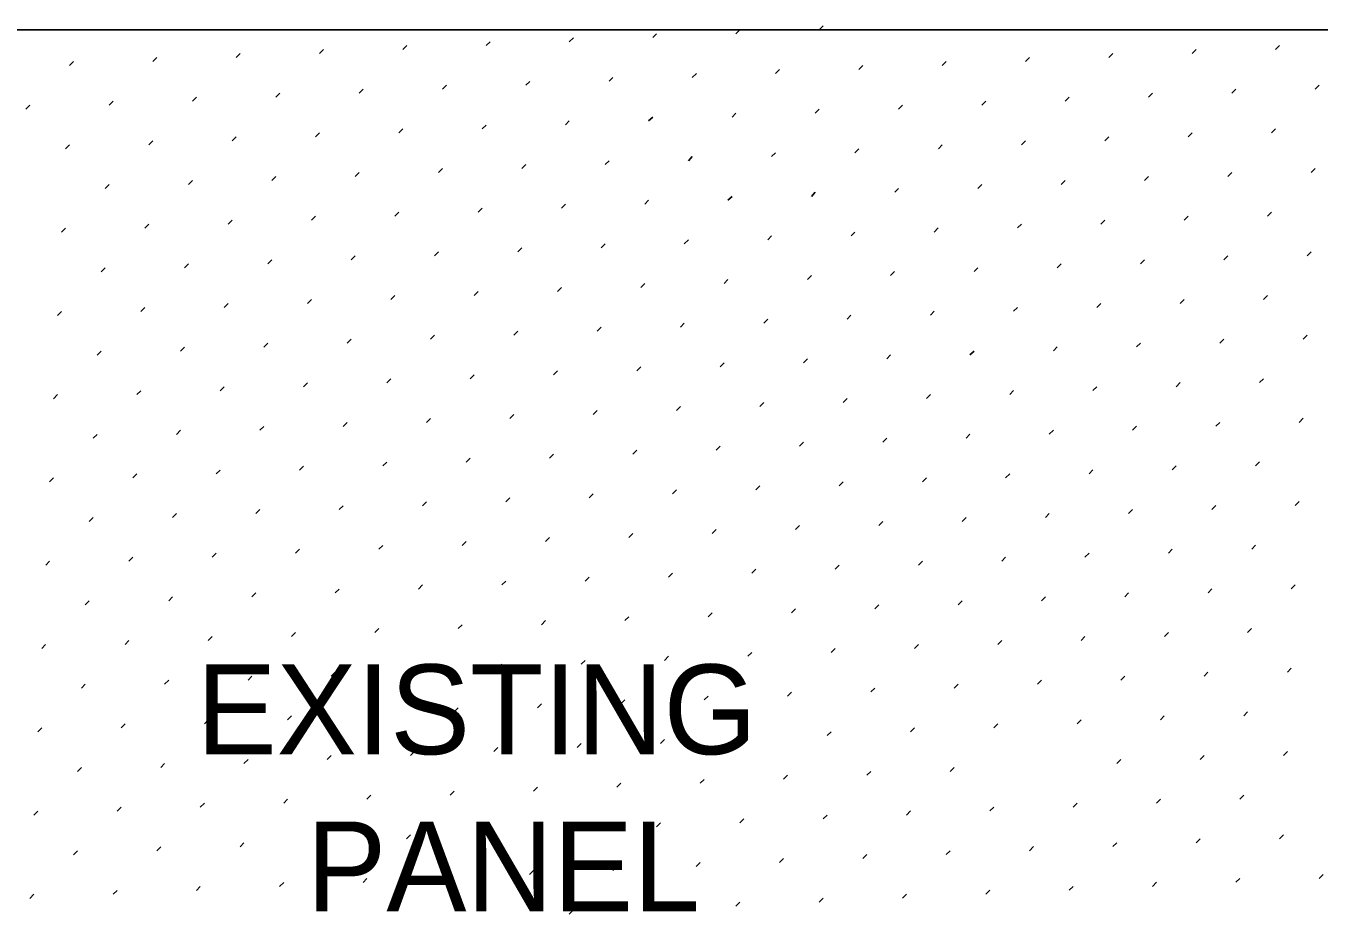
# Model space of a CAD drawing. Extents: x 49991.4 to 50021, y 49987.6 to 50011.4.
# Drawn here: x 50012.199 to 50013.352, y 49997.002 to 49997.794 of the extents above; entities that cross this region are included whole.
import ezdxf

# ---------------------------------------------------------------- set-up
doc = ezdxf.new("R2010")
doc.units = 0
for name, color, linetype in [('Level 1', 7, 'Continuous'), ('Level 10', 7, 'Continuous'), ('Level 2', 7, 'Continuous')]:
    doc.layers.add(name, color=color, linetype=linetype)

msp = doc.modelspace()

# ---------------------------------------------------------------- linework, layer by layer
at = {"layer": 'Level 1'}
msp.add_line((50011.6848, 49997.7903), (50015.1301, 49997.7903), dxfattribs=at)
at = {"layer": 'Level 10'}
for p, q in [((50012.9063, 49997.7902), (50012.9098, 49997.7938)), ((50012.6093, 49997.7761), (50012.6128, 49997.7796)), ((50012.6835, 49997.7796), (50012.6871, 49997.7831)), ((50012.7578, 49997.7832), (50012.7613, 49997.7867)), ((50012.832, 49997.7867), (50012.8356, 49997.7902)), ((50012.3865, 49997.7654), (50012.39, 49997.769)), ((50012.4608, 49997.769), (50012.4643, 49997.7725)), ((50012.535, 49997.7725), (50012.5386, 49997.7761)), ((50013.1644, 49997.7655), (50013.1679, 49997.769)), ((50013.2387, 49997.7691), (50013.2422, 49997.7726)), ((50013.3129, 49997.7726), (50013.3164, 49997.7761)), ((50012.238, 49997.7584), (50012.2415, 49997.7619)), ((50012.3123, 49997.7619), (50012.3158, 49997.7654)), ((50012.9416, 49997.7549), (50012.9452, 49997.7584)), ((50013.0159, 49997.7584), (50013.0194, 49997.762)), ((50013.0901, 49997.762), (50013.0937, 49997.7655)), ((50012.7189, 49997.7443), (50012.7224, 49997.7478)), ((50012.7931, 49997.7478), (50012.7967, 49997.7513)), ((50012.8674, 49997.7513), (50012.8709, 49997.7549)), ((50012.4219, 49997.7301), (50012.4254, 49997.7336)), ((50012.4961, 49997.7336), (50012.4997, 49997.7372)), ((50012.5704, 49997.7372), (50012.5739, 49997.7407)), ((50012.6446, 49997.7407), (50012.6482, 49997.7442)), ((50013.1998, 49997.7302), (50013.2033, 49997.7337)), ((50013.274, 49997.7337), (50013.2775, 49997.7372)), ((50013.3483, 49997.7372), (50013.3518, 49997.7408)), ((50012.1991, 49997.7195), (50012.2026, 49997.723)), ((50012.2734, 49997.723), (50012.2769, 49997.7265)), ((50012.3476, 49997.7265), (50012.3512, 49997.7301)), ((50012.977, 49997.7195), (50012.9805, 49997.7231)), ((50013.0512, 49997.7231), (50013.0548, 49997.7266)), ((50013.1255, 49997.7266), (50013.129, 49997.7301)), ((50012.7542, 49997.7089), (50012.7578, 49997.7124)), ((50012.8285, 49997.7124), (50012.832, 49997.716)), ((50012.9027, 49997.716), (50012.9063, 49997.7195)), ((50012.5315, 49997.6983), (50012.535, 49997.7018)), ((50012.6057, 49997.7018), (50012.6093, 49997.7053)), ((50012.68, 49997.7054), (50012.6835, 49997.7089)), ((50013.3094, 49997.6983), (50013.3129, 49997.7019)), ((50012.2345, 49997.6841), (50012.238, 49997.6876)), ((50012.3087, 49997.6876), (50012.3123, 49997.6912)), ((50012.383, 49997.6912), (50012.3865, 49997.6947)), ((50012.4572, 49997.6947), (50012.4608, 49997.6983)), ((50013.0124, 49997.6842), (50013.0159, 49997.6877)), ((50013.0866, 49997.6877), (50013.0901, 49997.6912)), ((50013.1609, 49997.6913), (50013.1644, 49997.6948)), ((50013.2351, 49997.6948), (50013.2386, 49997.6983)), ((50012.7896, 49997.6735), (50012.7931, 49997.6771)), ((50012.8638, 49997.6771), (50012.8674, 49997.6806)), ((50012.9381, 49997.6806), (50012.9416, 49997.6842)), ((50012.5668, 49997.6629), (50012.5704, 49997.6664)), ((50012.6411, 49997.6665), (50012.6446, 49997.67)), ((50012.7153, 49997.67), (50012.7189, 49997.6735)), ((50013.3447, 49997.663), (50013.3483, 49997.6665)), ((50012.3441, 49997.6523), (50012.3476, 49997.6558)), ((50012.4183, 49997.6558), (50012.4219, 49997.6594)), ((50012.4926, 49997.6594), (50012.4961, 49997.6629)), ((50013.122, 49997.6524), (50013.1255, 49997.6559)), ((50013.1962, 49997.6559), (50013.1997, 49997.6594)), ((50013.2705, 49997.6594), (50013.274, 49997.663)), ((50012.2698, 49997.6487), (50012.2734, 49997.6523)), ((50012.8249, 49997.6382), (50012.8285, 49997.6417)), ((50012.8992, 49997.6417), (50012.9027, 49997.6453)), ((50012.9735, 49997.6453), (50012.977, 49997.6488)), ((50013.0477, 49997.6488), (50013.0512, 49997.6523)), ((50012.6022, 49997.6276), (50012.6057, 49997.6311)), ((50012.6764, 49997.6311), (50012.68, 49997.6346)), ((50012.7507, 49997.6346), (50012.7542, 49997.6382)), ((50012.3794, 49997.6169), (50012.383, 49997.6205)), ((50012.4537, 49997.6205), (50012.4572, 49997.624)), ((50012.5279, 49997.624), (50012.5315, 49997.6276)), ((50013.1573, 49997.617), (50013.1609, 49997.6205)), ((50013.2316, 49997.6205), (50013.2351, 49997.6241)), ((50013.3058, 49997.6241), (50013.3094, 49997.6276)), ((50012.2309, 49997.6098), (50012.2345, 49997.6134)), ((50012.3052, 49997.6134), (50012.3087, 49997.6169)), ((50012.9346, 49997.6064), (50012.9381, 49997.6099)), ((50013.0088, 49997.6099), (50013.0123, 49997.6135)), ((50013.0831, 49997.6135), (50013.0866, 49997.617)), ((50012.6375, 49997.5922), (50012.6411, 49997.5957)), ((50012.7118, 49997.5957), (50012.7153, 49997.5993)), ((50012.786, 49997.5993), (50012.7896, 49997.6028)), ((50012.8603, 49997.6028), (50012.8638, 49997.6064)), ((50012.4148, 49997.5816), (50012.4183, 49997.5851)), ((50012.489, 49997.5851), (50012.4926, 49997.5887)), ((50012.5633, 49997.5887), (50012.5668, 49997.5922)), ((50013.1927, 49997.5816), (50013.1962, 49997.5852)), ((50013.2669, 49997.5852), (50013.2705, 49997.5887)), ((50013.3412, 49997.5887), (50013.3447, 49997.5923)), ((50012.2663, 49997.5745), (50012.2698, 49997.578)), ((50012.3405, 49997.578), (50012.3441, 49997.5816)), ((50012.9699, 49997.571), (50012.9734, 49997.5746)), ((50013.0442, 49997.5746), (50013.0477, 49997.5781)), ((50013.1184, 49997.5781), (50013.122, 49997.5816)), ((50012.7472, 49997.5604), (50012.7507, 49997.5639)), ((50012.8214, 49997.5639), (50012.8249, 49997.5675)), ((50012.8957, 49997.5675), (50012.8992, 49997.571)), ((50012.4501, 49997.5462), (50012.4537, 49997.5498)), ((50012.5244, 49997.5498), (50012.5279, 49997.5533)), ((50012.5986, 49997.5533), (50012.6022, 49997.5568)), ((50012.6729, 49997.5568), (50012.6764, 49997.5604)), ((50013.228, 49997.5463), (50013.2316, 49997.5498)), ((50013.3023, 49997.5498), (50013.3058, 49997.5534)), ((50012.2274, 49997.5356), (50012.2309, 49997.5391)), ((50012.3016, 49997.5391), (50012.3052, 49997.5427)), ((50012.3759, 49997.5427), (50012.3794, 49997.5462)), ((50013.0053, 49997.5357), (50013.0088, 49997.5392)), ((50013.0795, 49997.5392), (50013.0831, 49997.5427)), ((50013.1538, 49997.5427), (50013.1573, 49997.5463)), ((50012.7825, 49997.525), (50012.786, 49997.5286)), ((50012.8568, 49997.5286), (50012.8603, 49997.5321)), ((50012.931, 49997.5321), (50012.9345, 49997.5357)), ((50012.5597, 49997.5144), (50012.5633, 49997.5179)), ((50012.634, 49997.5179), (50012.6375, 49997.5215)), ((50012.7083, 49997.5215), (50012.7118, 49997.525)), ((50013.2634, 49997.5109), (50013.2669, 49997.5145)), ((50013.3376, 49997.5145), (50013.3412, 49997.518)), ((50012.2627, 49997.5002), (50012.2663, 49997.5038)), ((50012.337, 49997.5038), (50012.3405, 49997.5073)), ((50012.4112, 49997.5073), (50012.4148, 49997.5109)), ((50012.4855, 49997.5109), (50012.489, 49997.5144)), ((50013.0406, 49997.5003), (50013.0442, 49997.5038)), ((50013.1149, 49997.5039), (50013.1184, 49997.5074)), ((50013.1891, 49997.5074), (50013.1927, 49997.5109)), ((50012.8179, 49997.4897), (50012.8214, 49997.4932)), ((50012.8921, 49997.4932), (50012.8957, 49997.4968)), ((50012.9664, 49997.4968), (50012.9699, 49997.5003)), ((50012.5951, 49997.4791), (50012.5986, 49997.4826)), ((50012.6694, 49997.4826), (50012.6729, 49997.4861)), ((50012.7436, 49997.4861), (50012.7471, 49997.4897)), ((50012.2981, 49997.4649), (50012.3016, 49997.4684)), ((50012.3723, 49997.4684), (50012.3759, 49997.472)), ((50012.4466, 49997.472), (50012.4501, 49997.4755)), ((50012.5208, 49997.4755), (50012.5244, 49997.479)), ((50013.076, 49997.465), (50013.0795, 49997.4685)), ((50013.1502, 49997.4685), (50013.1538, 49997.472)), ((50013.2245, 49997.472), (50013.228, 49997.4756)), ((50013.2987, 49997.4756), (50013.3023, 49997.4791)), ((50012.2238, 49997.4613), (50012.2274, 49997.4649)), ((50012.8532, 49997.4543), (50012.8568, 49997.4579)), ((50012.9275, 49997.4579), (50012.931, 49997.4614)), ((50013.0017, 49997.4614), (50013.0053, 49997.4649)), ((50012.6305, 49997.4437), (50012.634, 49997.4472)), ((50012.7047, 49997.4472), (50012.7082, 49997.4508)), ((50012.779, 49997.4508), (50012.7825, 49997.4543)), ((50012.4077, 49997.4331), (50012.4112, 49997.4366)), ((50012.482, 49997.4366), (50012.4855, 49997.4401)), ((50012.5562, 49997.4402), (50012.5597, 49997.4437)), ((50013.1856, 49997.4331), (50013.1891, 49997.4367)), ((50013.2598, 49997.4367), (50013.2634, 49997.4402)), ((50013.3341, 49997.4402), (50013.3376, 49997.4438)), ((50012.2592, 49997.426), (50012.2627, 49997.4295)), ((50012.3334, 49997.4295), (50012.337, 49997.4331)), ((50012.8886, 49997.419), (50012.8921, 49997.4225)), ((50012.9628, 49997.4225), (50012.9664, 49997.426)), ((50013.0371, 49997.4261), (50013.0406, 49997.4296)), ((50013.1113, 49997.4296), (50013.1149, 49997.4331)), ((50012.6658, 49997.4083), (50012.6693, 49997.4119)), ((50012.7401, 49997.4119), (50012.7436, 49997.4154)), ((50012.8143, 49997.4154), (50012.8179, 49997.419)), ((50012.4431, 49997.3977), (50012.4466, 49997.4012)), ((50012.5173, 49997.4013), (50012.5208, 49997.4048)), ((50012.5916, 49997.4048), (50012.5951, 49997.4083)), ((50013.2209, 49997.3978), (50013.2245, 49997.4013)), ((50013.2952, 49997.4013), (50013.2987, 49997.4049)), ((50012.2203, 49997.3871), (50012.2238, 49997.3906)), ((50012.2945, 49997.3906), (50012.2981, 49997.3942)), ((50012.3688, 49997.3942), (50012.3723, 49997.3977)), ((50012.9982, 49997.3872), (50013.0017, 49997.3907)), ((50013.0724, 49997.3907), (50013.076, 49997.3942)), ((50013.1467, 49997.3942), (50013.1502, 49997.3978)), ((50012.7012, 49997.373), (50012.7047, 49997.3765)), ((50012.7754, 49997.3765), (50012.779, 49997.3801)), ((50012.8497, 49997.3801), (50012.8532, 49997.3836)), ((50012.9239, 49997.3836), (50012.9275, 49997.3871)), ((50012.4784, 49997.3624), (50012.4819, 49997.3659)), ((50012.5527, 49997.3659), (50012.5562, 49997.3694)), ((50012.6269, 49997.3694), (50012.6305, 49997.373)), ((50013.2563, 49997.3624), (50013.2598, 49997.366)), ((50013.3305, 49997.366), (50013.3341, 49997.3695)), ((50012.2556, 49997.3517), (50012.2592, 49997.3553)), ((50012.3299, 49997.3553), (50012.3334, 49997.3588)), ((50012.4042, 49997.3588), (50012.4077, 49997.3624)), ((50013.0335, 49997.3518), (50013.0371, 49997.3553)), ((50013.1078, 49997.3553), (50013.1113, 49997.3589)), ((50013.182, 49997.3589), (50013.1856, 49997.3624)), ((50012.8108, 49997.3412), (50012.8143, 49997.3447)), ((50012.885, 49997.3447), (50012.8886, 49997.3483)), ((50012.9593, 49997.3483), (50012.9628, 49997.3518)), ((50012.5138, 49997.327), (50012.5173, 49997.3305)), ((50012.588, 49997.3305), (50012.5916, 49997.3341)), ((50012.6623, 49997.3341), (50012.6658, 49997.3376)), ((50012.7365, 49997.3376), (50012.7401, 49997.3412)), ((50013.2917, 49997.3271), (50013.2952, 49997.3306)), ((50012.291, 49997.3164), (50012.2945, 49997.3199)), ((50012.3653, 49997.3199), (50012.3688, 49997.3235)), ((50012.4395, 49997.3235), (50012.443, 49997.327)), ((50013.0689, 49997.3164), (50013.0724, 49997.32)), ((50013.1431, 49997.32), (50013.1467, 49997.3235)), ((50013.2174, 49997.3235), (50013.2209, 49997.3271)), ((50012.2168, 49997.3128), (50012.2203, 49997.3164)), ((50012.8461, 49997.3058), (50012.8497, 49997.3094)), ((50012.9204, 49997.3094), (50012.9239, 49997.3129)), ((50012.9946, 49997.3129), (50012.9982, 49997.3164)), ((50012.6234, 49997.2952), (50012.6269, 49997.2987)), ((50012.6976, 49997.2987), (50012.7012, 49997.3023)), ((50012.7719, 49997.3023), (50012.7754, 49997.3058)), ((50012.3264, 49997.281), (50012.3299, 49997.2846)), ((50012.4006, 49997.2846), (50012.4041, 49997.2881)), ((50012.4749, 49997.2881), (50012.4784, 49997.2916)), ((50012.5491, 49997.2916), (50012.5527, 49997.2952)), ((50013.1042, 49997.2811), (50013.1078, 49997.2846)), ((50013.1785, 49997.2846), (50013.182, 49997.2882)), ((50013.2528, 49997.2882), (50013.2563, 49997.2917)), ((50013.327, 49997.2917), (50013.3305, 49997.2953)), ((50012.2521, 49997.2775), (50012.2556, 49997.281)), ((50012.8815, 49997.2705), (50012.885, 49997.274)), ((50012.9557, 49997.274), (50012.9593, 49997.2775)), ((50013.03, 49997.2775), (50013.0335, 49997.2811)), ((50012.6587, 49997.2598), (50012.6623, 49997.2634)), ((50012.733, 49997.2634), (50012.7365, 49997.2669)), ((50012.8072, 49997.2669), (50012.8108, 49997.2705)), ((50012.436, 49997.2492), (50012.4395, 49997.2527)), ((50012.5102, 49997.2527), (50012.5138, 49997.2563)), ((50012.5845, 49997.2563), (50012.588, 49997.2598)), ((50013.2139, 49997.2493), (50013.2174, 49997.2528)), ((50013.2881, 49997.2528), (50013.2916, 49997.2564)), ((50012.2132, 49997.2386), (50012.2167, 49997.2421)), ((50012.2875, 49997.2421), (50012.291, 49997.2457)), ((50012.3617, 49997.2457), (50012.3653, 49997.2492)), ((50012.9168, 49997.2351), (50012.9204, 49997.2386)), ((50012.9911, 49997.2386), (50012.9946, 49997.2422)), ((50013.0653, 49997.2422), (50013.0689, 49997.2457)), ((50013.1396, 49997.2457), (50013.1431, 49997.2493)), ((50012.6941, 49997.2245), (50012.6976, 49997.228)), ((50012.7683, 49997.228), (50012.7719, 49997.2316)), ((50012.8426, 49997.2316), (50012.8461, 49997.2351)), ((50012.4713, 49997.2139), (50012.4749, 49997.2174)), ((50012.5456, 49997.2174), (50012.5491, 49997.2209)), ((50012.6198, 49997.2209), (50012.6234, 49997.2245)), ((50013.2492, 49997.2139), (50013.2527, 49997.2175)), ((50013.3235, 49997.2175), (50013.327, 49997.221)), ((50012.2486, 49997.2032), (50012.2521, 49997.2068)), ((50012.3228, 49997.2068), (50012.3264, 49997.2103)), ((50012.3971, 49997.2103), (50012.4006, 49997.2138)), ((50012.9522, 49997.1998), (50012.9557, 49997.2033)), ((50013.0265, 49997.2033), (50013.03, 49997.2068)), ((50013.1007, 49997.2068), (50013.1042, 49997.2104)), ((50013.175, 49997.2104), (50013.1785, 49997.2139)), ((50012.7294, 49997.1891), (50012.733, 49997.1927)), ((50012.8037, 49997.1927), (50012.8072, 49997.1962)), ((50012.8779, 49997.1962), (50012.8815, 49997.1997)), ((50012.5067, 49997.1785), (50012.5102, 49997.182)), ((50012.5809, 49997.182), (50012.5845, 49997.1856)), ((50012.6552, 49997.1856), (50012.6587, 49997.1891)), ((50013.2846, 49997.1786), (50013.2881, 49997.1821)), ((50012.2839, 49997.1679), (50012.2875, 49997.1714)), ((50012.3582, 49997.1714), (50012.3617, 49997.1749)), ((50012.4324, 49997.175), (50012.436, 49997.1785)), ((50013.0618, 49997.1679), (50013.0653, 49997.1715)), ((50013.1361, 49997.1715), (50013.1396, 49997.175)), ((50013.2103, 49997.175), (50013.2138, 49997.1786)), ((50012.2097, 49997.1643), (50012.2132, 49997.1679)), ((50012.7648, 49997.1538), (50012.7683, 49997.1573)), ((50012.839, 49997.1573), (50012.8426, 49997.1608)), ((50012.9133, 49997.1609), (50012.9168, 49997.1644)), ((50012.9876, 49997.1644), (50012.9911, 49997.1679)), ((50012.542, 49997.1431), (50012.5456, 49997.1467)), ((50012.6163, 49997.1467), (50012.6198, 49997.1502)), ((50012.6905, 49997.1502), (50012.6941, 49997.1538)), ((50013.3199, 49997.1432), (50013.3235, 49997.1467)), ((50012.3193, 49997.1325), (50012.3228, 49997.136)), ((50012.3935, 49997.1361), (50012.3971, 49997.1396)), ((50012.4678, 49997.1396), (50012.4713, 49997.1431)), ((50013.1714, 49997.1361), (50013.175, 49997.1397)), ((50013.2457, 49997.1397), (50013.2492, 49997.1432)), ((50012.245, 49997.129), (50012.2486, 49997.1325)), ((50012.8744, 49997.122), (50012.8779, 49997.1255)), ((50012.9487, 49997.1255), (50012.9522, 49997.129)), ((50013.0229, 49997.129), (50013.0264, 49997.1326)), ((50012.5774, 49997.1078), (50012.5809, 49997.1113)), ((50012.6516, 49997.1113), (50012.6552, 49997.1149)), ((50012.7259, 49997.1149), (50012.7294, 49997.1184)), ((50012.8001, 49997.1184), (50012.8037, 49997.1219)), ((50012.3546, 49997.0972), (50012.3582, 49997.1007)), ((50012.4289, 49997.1007), (50012.4324, 49997.1042)), ((50012.5031, 49997.1042), (50012.5067, 49997.1078)), ((50013.1325, 49997.0972), (50013.1361, 49997.1008)), ((50013.2068, 49997.1008), (50013.2103, 49997.1043)), ((50013.281, 49997.1043), (50013.2846, 49997.1078)), ((50012.2061, 49997.0901), (50012.2097, 49997.0936)), ((50012.2804, 49997.0936), (50012.2839, 49997.0972)), ((50012.9098, 49997.0866), (50012.9133, 49997.0901)), ((50012.984, 49997.0901), (50012.9875, 49997.0937)), ((50013.0583, 49997.0937), (50013.0618, 49997.0972)), ((50012.687, 49997.076), (50012.6905, 49997.0795)), ((50012.7613, 49997.0795), (50012.7648, 49997.0831)), ((50012.8355, 49997.0831), (50012.839, 49997.0866)), ((50012.39, 49997.0618), (50012.3935, 49997.0653)), ((50012.4642, 49997.0653), (50012.4678, 49997.0689)), ((50012.5385, 49997.0689), (50012.542, 49997.0724)), ((50012.6127, 49997.0724), (50012.6163, 49997.076)), ((50013.1679, 49997.0619), (50013.1714, 49997.0654)), ((50013.2421, 49997.0654), (50013.2457, 49997.069)), ((50013.3164, 49997.069), (50013.3199, 49997.0725)), ((50012.2415, 49997.0547), (50012.245, 49997.0583)), ((50012.3157, 49997.0583), (50012.3193, 49997.0618)), ((50012.9451, 49997.0512), (50012.9486, 49997.0548)), ((50013.0194, 49997.0548), (50013.0229, 49997.0583)), ((50013.0936, 49997.0583), (50013.0972, 49997.0619)), ((50012.7224, 49997.0406), (50012.7259, 49997.0442)), ((50012.7966, 49997.0442), (50012.8001, 49997.0477)), ((50012.8709, 49997.0477), (50012.8744, 49997.0512)), ((50012.4996, 49997.03), (50012.5031, 49997.0335)), ((50012.5738, 49997.0335), (50012.5774, 49997.0371)), ((50012.6481, 49997.0371), (50012.6516, 49997.0406)), ((50013.2775, 49997.0301), (50013.281, 49997.0336)), ((50013.3517, 49997.0336), (50013.3553, 49997.0371)), ((50012.2026, 49997.0158), (50012.2061, 49997.0194)), ((50012.2768, 49997.0194), (50012.2804, 49997.0229)), ((50012.3511, 49997.0229), (50012.3546, 49997.0264)), ((50012.4253, 49997.0264), (50012.4289, 49997.03)), ((50012.9805, 49997.0159), (50012.984, 49997.0194)), ((50013.0547, 49997.0194), (50013.0583, 49997.023)), ((50013.129, 49997.023), (50013.1325, 49997.0265)), ((50013.2032, 49997.0265), (50013.2068, 49997.0301)), ((50012.7577, 49997.0053), (50012.7612, 49997.0088)), ((50012.832, 49997.0088), (50012.8355, 49997.0123)), ((50012.9062, 49997.0123), (50012.9098, 49997.0159)), ((50012.6835, 49997.0017), (50012.687, 49997.0053))]:
    msp.add_line(p, q, dxfattribs=at)

# ---------------------------------------------------------------- texts
at = {"layer": 'Level 2'}
for s, p in [('EXISTING', (50012.3513, 49997.1443)), ('PANEL', (50012.4491, 49997.0043))]:
    msp.add_text(s, height=0.08, dxfattribs=at).set_placement(p)

doc.saveas('drawing.dxf')
